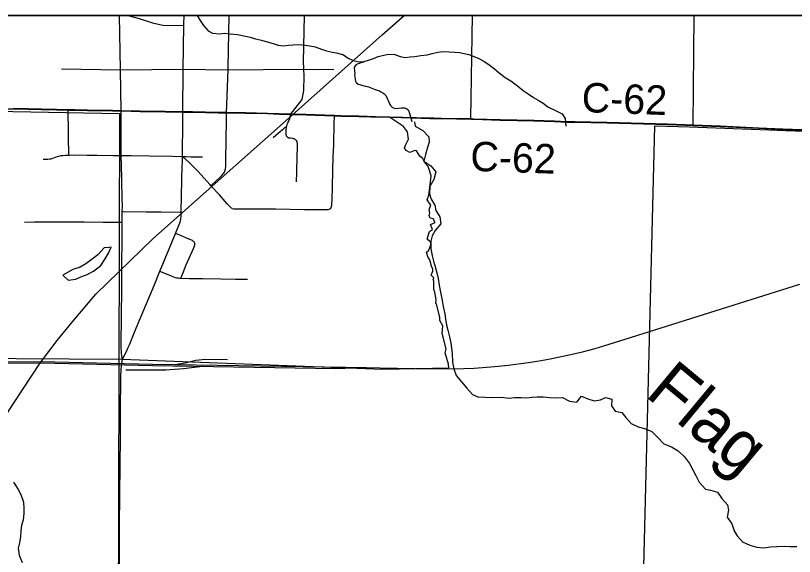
# Model space of a CAD drawing. Extents: x 0 to 34, y 0 to 22.
# Drawn here: x 7.175 to 7.927, y 20.378 to 20.9 of the extents above; entities that cross this region are included whole.
import ezdxf

# ---------------------------------------------------------------- set-up
doc = ezdxf.new("R2010")
doc.units = 0
for name, color, linetype in [('GM_X_City_Street', 7, 'Continuous'), ('GM_X_Corporation', 7, 'Continuous'), ('GM_X_County_Road', 7, 'Continuous'), ('GM_X_County_Road_Text', 7, 'Continuous'), ('GM_X_Minor_Lake', 7, 'Continuous'), ('GM_X_Minor_River', 7, 'Continuous'), ('GM_X_Minor_River_Text', 7, 'Continuous'), ('GM_X_Rail_Line', 7, 'Continuous'), ('GM_X_State_Route', 7, 'Continuous'), ('GM_X_Township_Road', 7, 'Continuous'), ('SH_Data', 7, 'Continuous')]:
    doc.layers.add(name, color=color, linetype=linetype)

msp = doc.modelspace()

# ---------------------------------------------------------------- linework, layer by layer
at = {"layer": 'GM_X_City_Street'}
msp.add_line((7.38037, 20.84947), (7.38112, 20.9), dxfattribs=at)
for points in [[(7.27687, 20.80798), (7.27626, 20.84776), (7.27527, 20.9)], [(7.28345, 20.9), (7.29447, 20.89731), (7.30733, 20.89298), (7.31724, 20.89072), (7.33747, 20.89037)], [(7.45335, 20.84927), (7.45315, 20.85552), (7.45407, 20.9)], [(7.21952, 20.84868), (7.27626, 20.84776), (7.33671, 20.84832), (7.38034, 20.84753), (7.41394, 20.84786)], [(7.37869, 20.80611), (7.38034, 20.84753), (7.38037, 20.84947)], [(7.41394, 20.84786), (7.45338, 20.84823), (7.46241, 20.848), (7.48214, 20.84831)], [(7.44033, 20.8047), (7.45156, 20.81917), (7.45346, 20.82782), (7.45376, 20.84186), (7.45338, 20.84823), (7.45335, 20.84927)], [(7.22679, 20.76544), (7.22663, 20.76726), (7.2264, 20.77066), (7.2261, 20.7778), (7.22606, 20.78576), (7.22602, 20.79417), (7.22598, 20.80167), (7.22593, 20.80795), (7.22592, 20.80892)], [(7.27821, 20.56819), (7.27761, 20.57171), (7.27736, 20.57423), (7.27698, 20.58087), (7.27707, 20.58897), (7.27737, 20.60385), (7.27735, 20.61066), (7.27752, 20.636), (7.27752, 20.65292), (7.27795, 20.6907), (7.27802, 20.70078), (7.27807, 20.70547), (7.27808, 20.70825), (7.27811, 20.7111), (7.27814, 20.716), (7.27801, 20.72305), (7.27765, 20.74147), (7.27718, 20.75677), (7.27709, 20.76345), (7.27707, 20.76509), (7.27691, 20.77635), (7.27688, 20.79789), (7.27687, 20.80702), (7.27687, 20.80798)], [(7.3637, 20.73582), (7.36435, 20.73647), (7.36874, 20.74061), (7.37148, 20.7432), (7.3742, 20.74576), (7.3755, 20.7472), (7.3762, 20.74812), (7.37672, 20.74902), (7.37721, 20.75005), (7.37748, 20.75087), (7.37775, 20.75186), (7.37785, 20.7528), (7.37799, 20.75414), (7.37804, 20.75534), (7.37802, 20.75972), (7.37807, 20.7671), (7.3782, 20.77377), (7.37844, 20.78564), (7.37857, 20.79307), (7.37873, 20.80012), (7.37869, 20.80611)], [(7.44612, 20.73953), (7.44649, 20.74888), (7.44682, 20.76422), (7.44717, 20.77288), (7.44714, 20.77572), (7.44707, 20.7767), (7.44701, 20.77722), (7.44692, 20.77775), (7.4468, 20.77818), (7.44664, 20.77859), (7.44641, 20.77907), (7.44609, 20.77949), (7.44575, 20.77989), (7.44536, 20.78022), (7.44491, 20.78053), (7.4445, 20.78077), (7.44406, 20.78098), (7.44347, 20.78118), (7.44261, 20.78135), (7.44056, 20.78161), (7.43951, 20.78175), (7.43893, 20.78184), (7.43845, 20.78199), (7.43808, 20.78215), (7.43772, 20.7824), (7.43742, 20.78266), (7.4372, 20.78293), (7.43693, 20.78328), (7.4367, 20.78363), (7.4365, 20.78412), (7.43642, 20.78474), (7.43637, 20.78526), (7.43636, 20.78645), (7.43637, 20.78819), (7.43642, 20.79021), (7.43654, 20.79161), (7.43674, 20.7929), (7.43687, 20.79342), (7.43707, 20.79416), (7.43734, 20.79503), (7.43752, 20.79559), (7.43783, 20.79637), (7.43865, 20.79822), (7.43967, 20.8005), (7.43992, 20.80117), (7.44008, 20.80179), (7.44021, 20.80276), (7.44033, 20.8047)], [(7.47937, 20.71426), (7.47982, 20.71496), (7.4801, 20.71578), (7.48031, 20.71677), (7.48043, 20.71785), (7.48065, 20.72338), (7.48085, 20.73429), (7.48133, 20.75107), (7.48174, 20.76366), (7.48212, 20.77541), (7.48272, 20.79664), (7.48288, 20.80227), (7.48291, 20.80322)], [(7.42385, 20.78255), (7.43077, 20.78838), (7.434, 20.79115), (7.43507, 20.79202), (7.43556, 20.79238), (7.43619, 20.79274), (7.43674, 20.7929)], [(7.20184, 20.76161), (7.20619, 20.76154), (7.20811, 20.76171), (7.20944, 20.76193), (7.21089, 20.76237), (7.21267, 20.76303), (7.21437, 20.76374), (7.21671, 20.76441), (7.21894, 20.76487), (7.22071, 20.76514), (7.22313, 20.76533), (7.22554, 20.76542), (7.22679, 20.76544), (7.23236, 20.76551), (7.24416, 20.76527), (7.2538, 20.76521), (7.26903, 20.76513), (7.27707, 20.76509), (7.28671, 20.76504), (7.30444, 20.76468), (7.32662, 20.76423), (7.33621, 20.76415)], [(7.38429, 20.71389), (7.38349, 20.71433), (7.38281, 20.71482), (7.38145, 20.71605), (7.37936, 20.71853), (7.37177, 20.72715), (7.3637, 20.73582), (7.36289, 20.73669), (7.35106, 20.7498), (7.34591, 20.75509), (7.34277, 20.7583), (7.33621, 20.76415)], [(7.33621, 20.76415), (7.3398, 20.76397), (7.34418, 20.76386), (7.34936, 20.76374), (7.35542, 20.76359)], [(7.38429, 20.71389), (7.38553, 20.71365), (7.38892, 20.71359), (7.39484, 20.71357), (7.40847, 20.71354), (7.42586, 20.71347), (7.45399, 20.71304), (7.47513, 20.71283), (7.47612, 20.71291), (7.47691, 20.71304), (7.47776, 20.71323), (7.47854, 20.71365), (7.47937, 20.71426)], [(7.27811, 20.7111), (7.27884, 20.71108), (7.30108, 20.71065), (7.31534, 20.71053), (7.33386, 20.71048), (7.33495, 20.71049)], [(7.18361, 20.70081), (7.19339, 20.70089), (7.21363, 20.70093), (7.2298, 20.70093), (7.24144, 20.70092), (7.25953, 20.70085), (7.27705, 20.70078), (7.27802, 20.70078)], [(7.33472, 20.6467), (7.33707, 20.65282), (7.33957, 20.65878), (7.34267, 20.66588), (7.3455, 20.67237), (7.3468, 20.67537), (7.34751, 20.67704), (7.34781, 20.67787), (7.34802, 20.6785), (7.34817, 20.67914), (7.3482, 20.67962), (7.34815, 20.68007), (7.34806, 20.68052), (7.34788, 20.681), (7.34759, 20.68141), (7.34733, 20.68177), (7.34693, 20.68216), (7.34642, 20.68253), (7.34571, 20.68294), (7.34478, 20.68337), (7.33935, 20.68567), (7.33363, 20.68804), (7.33035, 20.68932), (7.32941, 20.68969)], [(7.31435, 20.65338), (7.31512, 20.65306), (7.32512, 20.64879), (7.32808, 20.6477), (7.33054, 20.64709), (7.3319, 20.64689), (7.33337, 20.64674), (7.33472, 20.6467), (7.34271, 20.64647), (7.35569, 20.64643), (7.37311, 20.64611), (7.38747, 20.64584), (7.39896, 20.64568)]]:
    msp.add_lwpolyline(points, dxfattribs=at)
at = {"layer": 'GM_X_Corporation'}
for points in [[(8.9, 20.9), (2.1, 20.9)], [(8.9, 20.9), (6.79968, 20.9)], [(7.02214, 20.57001), (7.2781, 20.56846), (7.52957, 20.55902), (7.59323, 20.56017), (7.59299, 20.56366), (7.58983, 20.57468), (7.59086, 20.57852), (7.58799, 20.58853), (7.58682, 20.59322), (7.58746, 20.60058), (7.58471, 20.60598), (7.58471, 20.60872), (7.58178, 20.62049), (7.58065, 20.62278), (7.58111, 20.62568), (7.57963, 20.6333), (7.5788, 20.63572), (7.57894, 20.64368), (7.57821, 20.64511), (7.57871, 20.64713), (7.5763, 20.64954), (7.57776, 20.65355), (7.57783, 20.65544), (7.57661, 20.65831), (7.57486, 20.66442), (7.57322, 20.6665), (7.57185, 20.67163), (7.5741, 20.67366), (7.57601, 20.6789), (7.57577, 20.68126), (7.57287, 20.68369), (7.57237, 20.68438), (7.57458, 20.69163), (7.57745, 20.6938), (7.57562, 20.69857), (7.58024, 20.70053), (7.57827, 20.70409), (7.57528, 20.70462), (7.57421, 20.70715), (7.575, 20.70958), (7.57425, 20.71309), (7.57581, 20.71716), (7.57251, 20.72224), (7.57408, 20.72681), (7.57532, 20.73687), (7.57622, 20.74544), (7.57436, 20.75151), (7.57332, 20.75455), (7.57009, 20.75801), (7.56824, 20.76217), (7.56518, 20.76423), (7.56219, 20.76961), (7.56032, 20.76988), (7.55556, 20.76776), (7.55203, 20.76997), (7.55061, 20.77243), (7.55134, 20.77498), (7.55445, 20.78083), (7.55334, 20.78785), (7.5495, 20.79313), (7.53612, 20.80213), (7.53676, 20.80211), (7.57648, 20.80117), (7.61465, 20.80026), (7.61604, 20.9), (7.07654, 20.9)], [(7.95317, 20.78903), (7.91559, 20.79048), (7.89262, 20.79152), (7.85505, 20.79317), (7.82904, 20.79431), (7.82151, 20.79464), (7.80443, 20.79526), (7.74603, 20.79685), (7.71496, 20.79753), (7.70719, 20.7976), (7.69507, 20.798), (7.67519, 20.79866), (7.64288, 20.79951), (7.61741, 20.8002), (7.61465, 20.80026), (7.58605, 20.80083), (7.57891, 20.80099), (7.57487, 20.80109), (7.53612, 20.80213), (7.52251, 20.80245), (7.50656, 20.80289), (7.48911, 20.80337), (7.4828, 20.8035), (7.47342, 20.80382), (7.45539, 20.80444), (7.44022, 20.80498), (7.42932, 20.80531), (7.41815, 20.80568), (7.39701, 20.80605), (7.38214, 20.80631), (7.37858, 20.80639), (7.37068, 20.80654), (7.35852, 20.80678), (7.3459, 20.80702), (7.33631, 20.80704), (7.31953, 20.80742), (7.29518, 20.8079), (7.27762, 20.80824), (7.27676, 20.80825), (7.26863, 20.80835), (7.25752, 20.80857), (7.24436, 20.80884), (7.23218, 20.80907), (7.22682, 20.80918), (7.22581, 20.8092), (7.21452, 20.8094), (7.19996, 20.80975), (7.17346, 20.81025)], [(7.17346, 20.81025), (7.19996, 20.80975), (7.21452, 20.8094), (7.22581, 20.8092), (7.22682, 20.80918), (7.23218, 20.80907), (7.24436, 20.80884), (7.25752, 20.80857), (7.26863, 20.80835), (7.27676, 20.80825), (7.27762, 20.80824), (7.29518, 20.8079), (7.31953, 20.80742), (7.33631, 20.80704), (7.3459, 20.80702), (7.35852, 20.80678), (7.37068, 20.80654), (7.37858, 20.80639), (7.38214, 20.80631), (7.39701, 20.80605), (7.41815, 20.80568), (7.42932, 20.80531), (7.44022, 20.80498), (7.45539, 20.80444), (7.47342, 20.80382), (7.4828, 20.8035), (7.48911, 20.80337), (7.50656, 20.80289), (7.52251, 20.80245), (7.53612, 20.80213), (7.57487, 20.80109), (7.57891, 20.80099), (7.58605, 20.80083), (7.61465, 20.80026), (7.61741, 20.8002), (7.64288, 20.79951), (7.67519, 20.79866), (7.69507, 20.798), (7.70719, 20.7976), (7.71496, 20.79753), (7.74603, 20.79685), (7.80443, 20.79526), (7.82151, 20.79464), (7.82904, 20.79431), (7.85505, 20.79317), (7.89262, 20.79152), (7.91559, 20.79048), (7.95317, 20.78903)], [(7.17346, 20.81025), (7.19996, 20.80975), (7.21452, 20.8094), (7.22581, 20.8092), (7.22682, 20.80918), (7.23218, 20.80907), (7.24436, 20.80884), (7.25752, 20.80857), (7.26863, 20.80835), (7.27676, 20.80825), (7.27762, 20.80824), (7.29518, 20.8079), (7.31953, 20.80742), (7.33631, 20.80704), (7.3459, 20.80702), (7.35852, 20.80678), (7.37068, 20.80654), (7.37858, 20.80639), (7.38214, 20.80631), (7.39701, 20.80605), (7.41815, 20.80568), (7.42932, 20.80531), (7.44022, 20.80498), (7.45539, 20.80444), (7.47342, 20.80382), (7.4828, 20.8035), (7.48911, 20.80337), (7.50656, 20.80289), (7.52251, 20.80245), (7.53612, 20.80213), (7.57487, 20.80109), (7.57891, 20.80099), (7.58605, 20.80083), (7.61465, 20.80026), (7.61741, 20.8002), (7.64288, 20.79951), (7.67519, 20.79866), (7.69507, 20.798), (7.70719, 20.7976), (7.71496, 20.79753), (7.74603, 20.79685), (7.80443, 20.79526), (7.82151, 20.79464), (7.82904, 20.79431), (7.85505, 20.79317), (7.89262, 20.79152), (7.91559, 20.79048), (7.95317, 20.78903)], [(7.95317, 20.78903), (7.91559, 20.79048), (7.89262, 20.79152), (7.85505, 20.79317), (7.82904, 20.79431), (7.82151, 20.79464), (7.80443, 20.79526), (7.74603, 20.79685), (7.71496, 20.79753), (7.70719, 20.7976), (7.69507, 20.798), (7.67519, 20.79866), (7.64288, 20.79951), (7.61741, 20.8002), (7.61465, 20.80026), (7.58605, 20.80083), (7.57891, 20.80099), (7.57487, 20.80109), (7.53612, 20.80213), (7.52251, 20.80245), (7.50656, 20.80289), (7.48911, 20.80337), (7.4828, 20.8035), (7.47342, 20.80382), (7.45539, 20.80444), (7.44022, 20.80498), (7.42932, 20.80531), (7.41815, 20.80568), (7.39701, 20.80605), (7.38214, 20.80631), (7.37858, 20.80639), (7.37068, 20.80654), (7.35852, 20.80678), (7.3459, 20.80702), (7.33631, 20.80704), (7.31953, 20.80742), (7.29518, 20.8079), (7.27762, 20.80824), (7.27676, 20.80825), (7.26863, 20.80835), (7.25752, 20.80857), (7.24436, 20.80884), (7.23218, 20.80907), (7.22682, 20.80918), (7.22581, 20.8092), (7.21452, 20.8094), (7.19996, 20.80975), (7.17346, 20.81025)]]:
    msp.add_lwpolyline(points, dxfattribs=at)
for points in [[(6.7951, 20.81454), (7.27539, 20.80543), (7.27412, 20.31079), (6.77234, 20.31066)], [(7.82563, 20.79281), (8.30981, 20.77438), (8.29961, 20.30331), (7.77983, 20.30349), (7.79217, 20.79372)]]:
    msp.add_lwpolyline(points, close=True, dxfattribs=at)
at = {"layer": 'GM_X_County_Road'}
for p, q in [((7.32408, 20.80705), (7.33642, 20.80676)), ((7.53624, 20.80185), (7.55737, 20.80128))]:
    msp.add_line(p, q, dxfattribs=at)
for points in [[(7.16654, 20.81011), (7.17357, 20.80997), (7.20007, 20.80947), (7.21463, 20.80912), (7.22592, 20.80892)], [(7.22592, 20.80892), (7.22693, 20.8089), (7.23229, 20.8088), (7.24447, 20.80856), (7.25763, 20.8083), (7.26874, 20.80808), (7.27687, 20.80798)], [(7.27687, 20.80798), (7.27773, 20.80796), (7.29529, 20.80762), (7.30493, 20.80743)], [(7.30493, 20.80743), (7.31964, 20.80715), (7.32408, 20.80705)], [(7.33642, 20.80676), (7.34602, 20.80674), (7.35863, 20.8065), (7.37079, 20.80626), (7.37869, 20.80611)], [(7.37869, 20.80611), (7.38225, 20.80603), (7.39712, 20.80577), (7.41826, 20.8054), (7.42943, 20.80504), (7.44033, 20.8047)], [(7.44033, 20.8047), (7.4555, 20.80416), (7.47353, 20.80354), (7.48291, 20.80322)], [(7.48291, 20.80322), (7.48922, 20.8031), (7.50667, 20.80262), (7.51799, 20.8023)], [(7.51799, 20.8023), (7.52262, 20.80218), (7.53624, 20.80185)], [(7.55737, 20.80128), (7.57498, 20.80081), (7.57902, 20.80072), (7.57949, 20.80071)], [(7.57949, 20.80071), (7.58616, 20.80056), (7.61476, 20.79998)], [(7.61476, 20.79998), (7.61752, 20.79993), (7.64299, 20.79924), (7.6753, 20.79838), (7.69518, 20.79772), (7.7073, 20.79732), (7.71507, 20.79725), (7.74614, 20.79658), (7.80454, 20.79499), (7.82162, 20.79437), (7.82915, 20.79404)], [(7.82915, 20.79404), (7.85516, 20.7929), (7.89273, 20.79125), (7.9157, 20.7902), (7.95328, 20.78875)]]:
    msp.add_lwpolyline(points, dxfattribs=at)
at = {"layer": 'GM_X_Minor_Lake'}
for points in [[(7.22082, 20.64957), (7.22571, 20.6448), (7.23328, 20.6457), (7.23803, 20.64813), (7.2441, 20.65018), (7.25018, 20.65356), (7.25722, 20.65901), (7.26142, 20.66543), (7.26486, 20.67072), (7.26736, 20.67658), (7.26504, 20.67634)], [(7.26504, 20.67634), (7.26054, 20.67587), (7.25444, 20.66908), (7.24912, 20.66494), (7.24303, 20.66043), (7.23733, 20.65743), (7.2305, 20.6552), (7.22082, 20.64957)]]:
    msp.add_lwpolyline(points, dxfattribs=at)
at = {"layer": 'GM_X_Minor_River'}
for points in [[(7.35047, 20.9), (7.35329, 20.89517), (7.35646, 20.89039), (7.36096, 20.88541), (7.36529, 20.8829), (7.37192, 20.88245), (7.37686, 20.88296), (7.38216, 20.88234), (7.38917, 20.88169), (7.39693, 20.88028), (7.40147, 20.87928), (7.40658, 20.87771), (7.41244, 20.87631), (7.41792, 20.87474), (7.42359, 20.87297), (7.42851, 20.87159), (7.43362, 20.87096), (7.43856, 20.87148), (7.44311, 20.87181), (7.44881, 20.87213), (7.45449, 20.87131), (7.45903, 20.87088), (7.46433, 20.86987), (7.47037, 20.86753), (7.47529, 20.86596), (7.48096, 20.86457), (7.48626, 20.86375), (7.49174, 20.86218), (7.49607, 20.8589), (7.50079, 20.85676), (7.50514, 20.85577), (7.51007, 20.85552), (7.51482, 20.85661), (7.52053, 20.85864), (7.52511, 20.86068), (7.53062, 20.86176), (7.53518, 20.86285), (7.54106, 20.8624), (7.54635, 20.86064), (7.55108, 20.85964), (7.55583, 20.86016), (7.56038, 20.86049), (7.56627, 20.86137), (7.57235, 20.86207), (7.57711, 20.86354), (7.58262, 20.86481), (7.58794, 20.86551), (7.59324, 20.86507), (7.59893, 20.86463), (7.60348, 20.86439), (7.60821, 20.86358), (7.61256, 20.8624), (7.62162, 20.85888), (7.62709, 20.85617), (7.63311, 20.85193), (7.63744, 20.84865), (7.64194, 20.84462), (7.64758, 20.84038), (7.65323, 20.8369), (7.65944, 20.83209), (7.66508, 20.82767), (7.66978, 20.82439), (7.67487, 20.82111)], [(7.50213, 20.85018), (7.50446, 20.85298), (7.50599, 20.8539), (7.50866, 20.85461), (7.51018, 20.85495), (7.51171, 20.85568), (7.51228, 20.85602)], [(7.50205, 20.8504), (7.50224, 20.84639), (7.5024, 20.84487), (7.50236, 20.84297), (7.50252, 20.84164), (7.50283, 20.83822), (7.50318, 20.83688), (7.50391, 20.83554), (7.50577, 20.83399), (7.50727, 20.83358), (7.50934, 20.83278), (7.51254, 20.83196), (7.51461, 20.83154), (7.51593, 20.83113), (7.51724, 20.83054), (7.51893, 20.82993), (7.52044, 20.82933), (7.52232, 20.82873), (7.524, 20.82793), (7.52626, 20.82732), (7.52776, 20.82634), (7.52926, 20.82593), (7.53093, 20.82438), (7.53278, 20.82245), (7.53423, 20.81938), (7.53478, 20.81804), (7.53603, 20.8148), (7.53695, 20.81326), (7.53843, 20.81171), (7.54049, 20.81053), (7.54276, 20.81049), (7.54484, 20.81064), (7.5475, 20.81115), (7.55034, 20.81109), (7.55241, 20.81029), (7.5539, 20.80913), (7.55463, 20.80779), (7.55534, 20.80549), (7.55751, 20.79768), (7.55677, 20.80167)], [(7.67487, 20.82111), (7.67958, 20.8184), (7.68428, 20.8155), (7.68899, 20.81204), (7.69766, 20.80777), (7.70275, 20.80524), (7.70555, 20.80066), (7.70622, 20.79336)], [(7.56023, 20.79761), (7.56092, 20.7933), (7.56809, 20.78908), (7.57411, 20.78297), (7.57426, 20.77804), (7.57233, 20.7718), (7.57078, 20.76612), (7.56903, 20.75968), (7.57582, 20.7549), (7.5807, 20.74918), (7.57895, 20.74198), (7.57494, 20.73518), (7.5747, 20.72817), (7.57618, 20.72304), (7.57993, 20.71713), (7.58084, 20.71182), (7.58459, 20.70573), (7.58568, 20.69908), (7.58015, 20.69267), (7.57728, 20.68738), (7.57592, 20.68227), (7.57588, 20.67544), (7.57735, 20.66822), (7.57864, 20.6631), (7.58049, 20.65664), (7.5816, 20.6517), (7.58289, 20.64638), (7.58398, 20.63993), (7.58508, 20.6348), (7.586, 20.62987), (7.58692, 20.62512), (7.58782, 20.61942), (7.58929, 20.61221), (7.59002, 20.60746), (7.59112, 20.6012), (7.59222, 20.59645), (7.59388, 20.59018), (7.59536, 20.58392), (7.59653, 20.57389)], [(7.59653, 20.57389), (7.59679, 20.56563), (7.59827, 20.55936), (7.6005, 20.5529), (7.60538, 20.5468), (7.61064, 20.54052), (7.61628, 20.53442), (7.62119, 20.5323), (7.628, 20.53188), (7.63481, 20.53166), (7.6437, 20.53198), (7.65145, 20.53099), (7.65656, 20.53153), (7.66318, 20.5315), (7.6681, 20.53128), (7.67359, 20.53182), (7.67851, 20.53217), (7.68456, 20.53213), (7.69042, 20.53153), (7.6961, 20.53112), (7.7031, 20.53146), (7.7097, 20.52801), (7.71688, 20.52721), (7.72127, 20.53288), (7.72749, 20.53018), (7.73354, 20.52844), (7.73978, 20.52936), (7.74453, 20.53161), (7.75057, 20.53006), (7.75016, 20.52342), (7.75391, 20.51847), (7.76014, 20.51711), (7.76409, 20.51234), (7.76935, 20.50643), (7.77596, 20.50336), (7.78219, 20.50162), (7.78917, 20.49893), (7.79462, 20.4934), (7.80083, 20.48691), (7.80838, 20.48384), (7.8146, 20.4802), (7.82062, 20.47448), (7.82569, 20.468), (7.82906, 20.46116), (7.83186, 20.45621), (7.83504, 20.44974), (7.84106, 20.44307), (7.84597, 20.44229), (7.85258, 20.44035), (7.85671, 20.43426), (7.86216, 20.42797), (7.86326, 20.42304), (7.8619, 20.41622), (7.8664, 20.40956), (7.86863, 20.4029), (7.87163, 20.39815), (7.87689, 20.39224), (7.88369, 20.38898), (7.89067, 20.38723), (7.89729, 20.38662), (7.90392, 20.38735), (7.90978, 20.38788), (7.91754, 20.38803), (7.92284, 20.38781), (7.92927, 20.38796)], [(7.17313, 20.4499), (7.17763, 20.44286), (7.18025, 20.4381), (7.18267, 20.43069), (7.18301, 20.42481), (7.18317, 20.41969), (7.18238, 20.41363), (7.18083, 20.40814), (7.18005, 20.40321), (7.17982, 20.39752), (7.17884, 20.39146), (7.17768, 20.38616), (7.17839, 20.37933), (7.18157, 20.37229)]]:
    msp.add_lwpolyline(points, dxfattribs=at)
at = {"layer": 'GM_X_Rail_Line'}
for points in [[(7.43918, 20.80147), (7.52904, 20.88149), (7.55005, 20.9)], [(7.19919, 20.56539), (7.21532, 20.58653), (7.22978, 20.60413), (7.25257, 20.63126), (7.3076, 20.68449), (7.43918, 20.80147)], [(7.12635, 20.56433), (7.1993, 20.56511), (7.30725, 20.56257), (7.48424, 20.55961), (7.50997, 20.56045), (7.56052, 20.55962), (7.59766, 20.55934), (7.61772, 20.55997), (7.63757, 20.56135), (7.65057, 20.56273), (7.67014, 20.56529), (7.68231, 20.56723), (7.69269, 20.56916), (7.70956, 20.57262), (7.72243, 20.57567), (7.73446, 20.57899), (7.74283, 20.58127), (7.76344, 20.5877), (7.93215, 20.64094)], [(4.83086, 16.81428), (4.95348, 17.00356), (5.121, 17.25544), (5.31678, 17.55326), (5.45252, 17.7592), (5.58679, 17.98275), (5.74825, 18.23979), (5.90418, 18.49744), (6.02127, 18.68264), (6.13663, 18.87252), (6.2288, 19.01731), (6.34315, 19.20099), (6.38785, 19.27035), (6.55501, 19.53303), (6.71382, 19.79395), (6.76349, 19.87076), (6.84474, 20.00352), (6.94083, 20.16003), (7.03262, 20.3087), (7.17305, 20.5257), (7.19919, 20.56539)], [(6.26535, 20.53071), (6.48407, 20.5397), (6.63504, 20.54492), (6.68014, 20.54698), (6.80739, 20.55272), (6.89038, 20.55561), (6.93271, 20.55766), (6.98399, 20.55992), (7.03989, 20.56198), (7.08643, 20.56393), (7.12632, 20.56558), (7.1993, 20.56635), (7.30727, 20.56381), (7.45258, 20.56138), (7.51394, 20.56039)], [(7.2814, 20.55837), (7.30678, 20.55817), (7.32014, 20.55837), (7.3371, 20.5594), (7.3554, 20.56176)], [(7.32877, 20.56345), (7.33874, 20.56505), (7.34902, 20.56762), (7.35826, 20.56855), (7.37964, 20.56824)]]:
    msp.add_lwpolyline(points, dxfattribs=at)
at = {"layer": 'GM_X_State_Route'}
msp.add_line((7.33751, 20.89185), (7.33776, 20.9), dxfattribs=at)
for points in [[(7.33642, 20.80676), (7.33671, 20.84832), (7.33747, 20.89037), (7.33751, 20.89185)], [(7.33606, 20.76019), (7.33621, 20.76415), (7.33633, 20.76999), (7.3365, 20.79305), (7.33642, 20.80676)], [(7.333, 20.69848), (7.33365, 20.70017), (7.33425, 20.70203), (7.33454, 20.70333), (7.3347, 20.70453), (7.33478, 20.70588), (7.33487, 20.70719), (7.33491, 20.70902), (7.33495, 20.71049), (7.33504, 20.71365), (7.33521, 20.72285), (7.3355, 20.74482), (7.33606, 20.76019)], [(7.27821, 20.56819), (7.28089, 20.57358), (7.28255, 20.5767), (7.28359, 20.57911), (7.28502, 20.5825), (7.28996, 20.59459), (7.29569, 20.60851), (7.30077, 20.62063), (7.30524, 20.6314), (7.30873, 20.63972), (7.31435, 20.65338), (7.31712, 20.66009), (7.32563, 20.68047), (7.32941, 20.68969), (7.333, 20.69848)], [(7.27206, 20.05882), (7.27247, 20.08943), (7.27277, 20.11864), (7.27309, 20.16402), (7.27358, 20.21312), (7.27372, 20.23177), (7.27403, 20.26503), (7.27449, 20.31105), (7.27458, 20.31972), (7.275, 20.35889), (7.27527, 20.38313), (7.2755, 20.4074), (7.27584, 20.43875), (7.27625, 20.49345), (7.27633, 20.50495), (7.27638, 20.52142), (7.27655, 20.54796), (7.27673, 20.55223), (7.27693, 20.55811), (7.27716, 20.56216), (7.27755, 20.56486), (7.27821, 20.56819)]]:
    msp.add_lwpolyline(points, dxfattribs=at)
at = {"layer": 'GM_X_Township_Road'}
msp.add_line((7.82915, 20.79404), (7.83012, 20.9), dxfattribs=at)
at = {"layer": 'SH_Data'}
msp.add_line((2.1, 20.9), (8.9, 20.9), dxfattribs=at)

# ---------------------------------------------------------------- texts
at = {"layer": 'GM_X_County_Road_Text'}
for rotation, p in [(357.90649, (7.72117, 20.807)), (358.00364, (7.61372, 20.75026))]:
    msp.add_text('C-62', height=0.028409, rotation=rotation, dxfattribs=at).set_placement(p)
at = {"layer": 'GM_X_Minor_River_Text'}
msp.add_text('Flag', height=0.047375, rotation=320.20033, dxfattribs=at).set_placement((7.78172, 20.53357))

doc.saveas('drawing.dxf')
